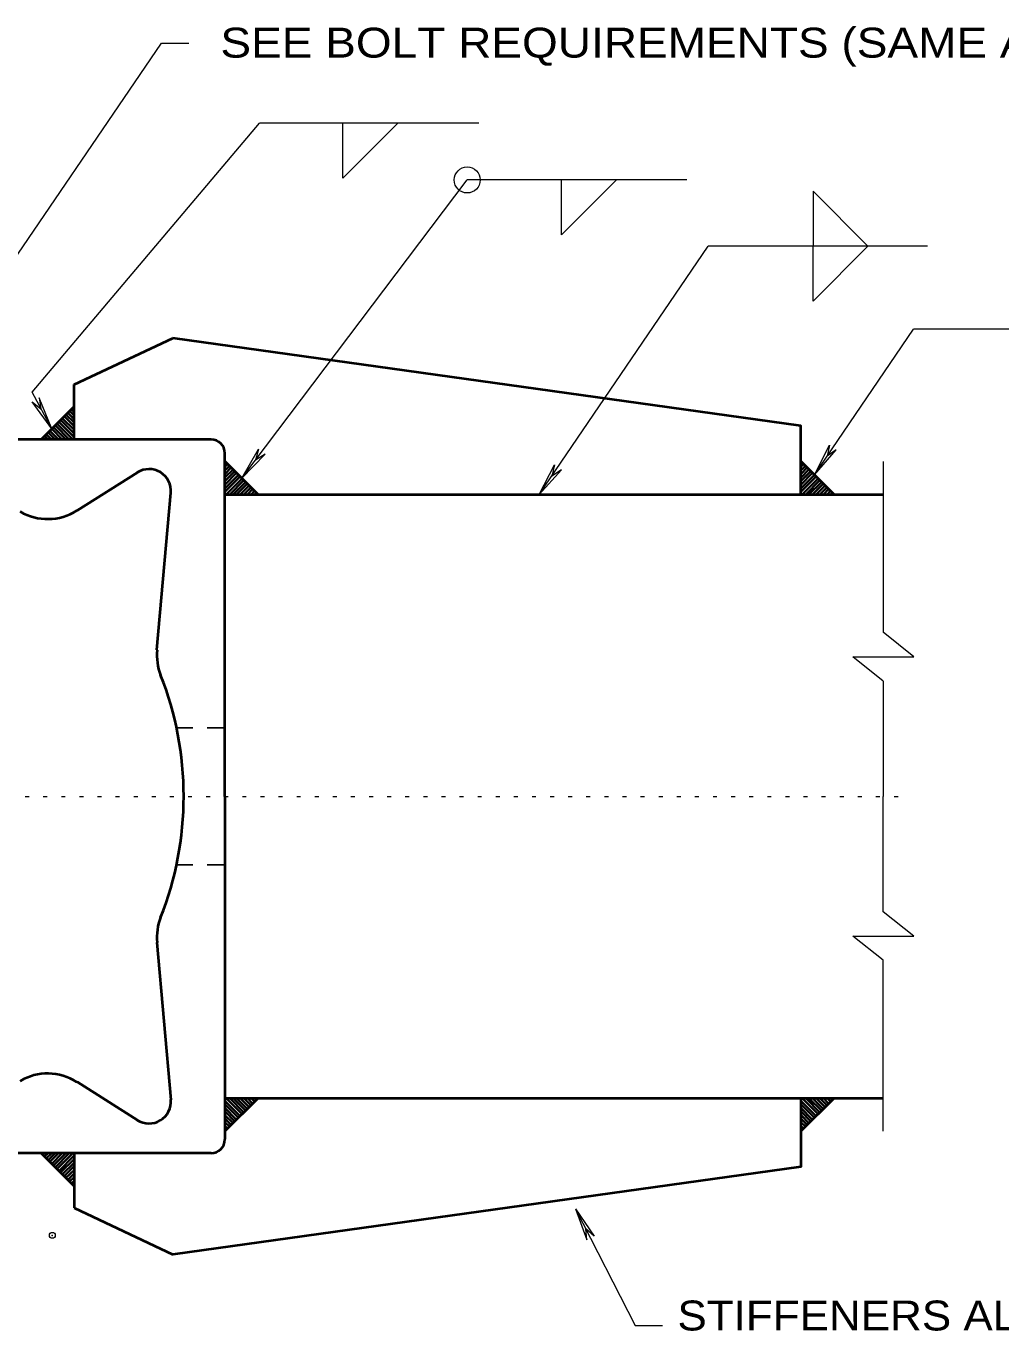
# Model space of a CAD drawing. Extents: x 312583 to 312854, y 144419 to 144597.
# Drawn here: x 312636.81 to 312661.58, y 144488.79 to 144521.92 of the extents above; entities that cross this region are included whole.
import ezdxf

# ---------------------------------------------------------------- set-up
doc = ezdxf.new("R2010")
doc.units = 0
doc.header["$LTSCALE"] = 0.3
doc.header["$PDMODE"] = 32
doc.header["$PDSIZE"] = 0.15
doc.linetypes.add('DOTTED', pattern=[1.5, 0.3, -1.2])
doc.linetypes.add('SHORT_DASHED', pattern=[2.7, 1.5, -1.2])
doc.layers.add('1', color=7, linetype='Continuous', lineweight=35)
doc.layers.add('2', color=7, linetype='Continuous', lineweight=13)

msp = doc.modelspace()

# ---------------------------------------------------------------- linework, layer by layer
at = {"layer": '1', "lineweight": 40}
for p, q in [((312638.0305, 144512.8216), (312640.5451, 144514.0023)), ((312638.0305, 144511.4263), (312638.0305, 144512.8216)), ((312637.1948, 144511.4263), (312638.0305, 144512.2619)), ((312641.5188, 144511.4263), (312635.2398, 144511.4263)), ((312641.8638, 144502.3643), (312641.8638, 144511.0813)), ((312642.7071, 144510.0309), (312641.8638, 144510.8743)), ((312657.3428, 144510.0309), (312656.4995, 144510.8743)), ((312638.1071, 144509.6246), (312639.6405, 144510.5906)), ((312640.1388, 144506.0826), (312640.4915, 144510.0693)), ((312641.8638, 144510.0309), (312658.5925, 144510.0309)), ((312641.8638, 144502.3643), (312641.8638, 144493.6549)), ((312640.1388, 144498.6536), (312640.4915, 144494.6593)), ((312638.1071, 144495.1116), (312639.6405, 144494.1456)), ((312641.8638, 144494.6976), (312658.5925, 144494.6976)), ((312642.7071, 144494.6976), (312641.8638, 144493.8619)), ((312657.3428, 144494.6976), (312656.4995, 144493.8619)), ((312641.5188, 144493.3023), (312635.2398, 144493.3023)), ((312637.1948, 144493.3023), (312638.0305, 144492.4666)), ((312638.0305, 144493.3023), (312638.0305, 144491.9146)), ((312638.0305, 144491.9146), (312640.5451, 144490.7263))]:
    msp.add_line(p, q, dxfattribs=at)
at = {"layer": '1'}
for p, q in [((312638.0305, 144511.6716), (312637.7315, 144511.9706)), ((312638.0305, 144511.7636), (312637.7775, 144512.0166)), ((312638.0305, 144511.8556), (312637.8235, 144512.0626)), ((312638.0305, 144511.9399), (312637.8695, 144512.1009)), ((312638.0305, 144512.0319), (312637.9155, 144512.1546)), ((312638.0305, 144512.1239), (312637.9615, 144512.1929)), ((312638.0305, 144512.2159), (312638.0075, 144512.2389)), ((312637.6395, 144511.4263), (312637.4171, 144511.6486)), ((312637.7315, 144511.4263), (312637.4631, 144511.6946)), ((312637.8235, 144511.4263), (312637.5091, 144511.7406)), ((312637.9078, 144511.4263), (312637.5551, 144511.7866)), ((312637.9998, 144511.4263), (312637.5935, 144511.8326)), ((312638.0305, 144511.4876), (312637.6471, 144511.8786)), ((312638.0305, 144511.5796), (312637.6855, 144511.9246)), ((312637.2791, 144511.4263), (312637.2331, 144511.4723)), ((312637.3711, 144511.4263), (312637.2791, 144511.5183)), ((312637.4631, 144511.4263), (312637.3251, 144511.5566)), ((312637.5475, 144511.4263), (312637.3711, 144511.6026)), ((312641.8638, 144510.8206), (312641.8868, 144510.8436)), ((312641.8638, 144510.7286), (312641.9405, 144510.8053)), ((312641.8638, 144510.6366), (312641.9788, 144510.7593)), ((312641.8638, 144510.5446), (312642.0248, 144510.7133)), ((312641.8638, 144510.4603), (312642.0708, 144510.6673)), ((312641.8638, 144510.3683), (312642.1168, 144510.6213)), ((312656.4995, 144510.8206), (312656.5225, 144510.8436)), ((312656.4995, 144510.7286), (312656.5761, 144510.8053)), ((312656.4995, 144510.6366), (312656.6145, 144510.7593)), ((312656.4995, 144510.5446), (312656.6605, 144510.7133)), ((312656.4995, 144510.3683), (312656.7525, 144510.6213)), ((312656.5071, 144510.4603), (312656.7065, 144510.6673)), ((312641.8638, 144510.2763), (312642.1628, 144510.5753)), ((312641.8638, 144510.1843), (312642.2088, 144510.5293)), ((312641.8638, 144510.0999), (312642.2548, 144510.4833)), ((312641.8945, 144510.0309), (312642.3008, 144510.4373)), ((312641.9865, 144510.0309), (312642.3468, 144510.3913)), ((312642.0708, 144510.0309), (312642.3851, 144510.3453)), ((312642.1628, 144510.0309), (312642.4311, 144510.2993)), ((312656.4995, 144510.2763), (312656.7985, 144510.5753)), ((312656.4995, 144510.1843), (312656.8445, 144510.5293)), ((312656.4995, 144510.0999), (312656.8905, 144510.4833)), ((312656.5301, 144510.0309), (312656.9365, 144510.4373)), ((312656.6221, 144510.0309), (312656.9825, 144510.3913)), ((312656.7065, 144510.0309), (312657.0285, 144510.3453)), ((312656.7985, 144510.0309), (312657.0668, 144510.2993)), ((312642.2548, 144510.0309), (312642.4771, 144510.2609)), ((312642.3468, 144510.0309), (312642.5231, 144510.2073)), ((312642.4388, 144510.0309), (312642.5691, 144510.1689)), ((312642.5308, 144510.0309), (312642.6151, 144510.1229)), ((312642.6151, 144510.0309), (312642.6611, 144510.0769)), ((312656.8905, 144510.0309), (312657.1205, 144510.2609)), ((312656.9825, 144510.0309), (312657.1588, 144510.2073)), ((312657.0745, 144510.0309), (312657.2048, 144510.1689)), ((312657.1665, 144510.0309), (312657.2508, 144510.1229)), ((312657.2508, 144510.0309), (312657.2968, 144510.0769)), ((312641.8638, 144494.6363), (312642.2548, 144494.2453)), ((312641.8638, 144494.5443), (312642.2088, 144494.1993)), ((312641.8638, 144494.4523), (312642.1628, 144494.1533)), ((312641.8945, 144494.6976), (312642.3008, 144494.2913)), ((312641.9865, 144494.6976), (312642.3468, 144494.3373)), ((312642.0708, 144494.6976), (312642.3851, 144494.3833)), ((312642.1628, 144494.6976), (312642.4311, 144494.4293)), ((312642.2548, 144494.6976), (312642.4771, 144494.4753)), ((312642.3468, 144494.6976), (312642.5231, 144494.5213)), ((312642.4388, 144494.6976), (312642.5691, 144494.5673)), ((312642.5308, 144494.6976), (312642.6151, 144494.6133)), ((312642.6151, 144494.6976), (312642.6611, 144494.6516)), ((312656.4995, 144494.6363), (312656.8905, 144494.2453)), ((312656.4995, 144494.5443), (312656.8445, 144494.1993)), ((312656.4995, 144494.4523), (312656.7985, 144494.1533)), ((312656.5301, 144494.6976), (312656.9365, 144494.2913)), ((312656.6221, 144494.6976), (312656.9825, 144494.3373)), ((312656.7065, 144494.6976), (312657.0285, 144494.3833)), ((312656.7985, 144494.6976), (312657.0668, 144494.4293)), ((312656.8905, 144494.6976), (312657.1205, 144494.4753)), ((312656.9825, 144494.6976), (312657.1588, 144494.5213)), ((312657.0745, 144494.6976), (312657.2048, 144494.5673)), ((312657.1665, 144494.6976), (312657.2508, 144494.6133)), ((312657.2508, 144494.6976), (312657.2968, 144494.6516)), ((312641.8638, 144494.3679), (312642.1168, 144494.1073)), ((312641.8638, 144494.2683), (312642.0708, 144494.0689)), ((312641.8638, 144494.1839), (312642.0248, 144494.0229)), ((312641.8638, 144494.0919), (312641.9788, 144493.9769)), ((312656.4995, 144494.3679), (312656.7525, 144494.1073)), ((312656.4995, 144494.1839), (312656.6605, 144494.0229)), ((312656.4995, 144494.0919), (312656.6145, 144493.9769)), ((312656.5071, 144494.2683), (312656.7065, 144494.0689)), ((312641.8638, 144493.9999), (312641.9405, 144493.9309)), ((312641.8638, 144493.9079), (312641.8868, 144493.8849)), ((312656.4995, 144493.9999), (312656.5761, 144493.9309)), ((312656.4995, 144493.9079), (312656.5225, 144493.8849)), ((312637.2791, 144493.3023), (312637.2331, 144493.2639)), ((312637.3711, 144493.3023), (312637.2791, 144493.2179)), ((312637.4631, 144493.3023), (312637.3251, 144493.1719)), ((312637.5475, 144493.3023), (312637.3711, 144493.1259)), ((312637.6395, 144493.3023), (312637.4171, 144493.0799)), ((312637.7315, 144493.3023), (312637.4631, 144493.0339)), ((312637.8235, 144493.3023), (312637.5091, 144492.9879)), ((312637.9078, 144493.3023), (312637.5551, 144492.9419)), ((312637.9998, 144493.3023), (312637.5935, 144492.8959)), ((312638.0305, 144493.2409), (312637.6471, 144492.8499)), ((312638.0305, 144493.1489), (312637.6855, 144492.8116)), ((312638.0305, 144493.0569), (312637.7315, 144492.7579)), ((312638.0305, 144492.9726), (312637.7775, 144492.7196)), ((312638.0305, 144492.8729), (312637.8235, 144492.6736)), ((312638.0305, 144492.7886), (312637.8695, 144492.6276)), ((312638.0305, 144492.6966), (312637.9155, 144492.5816)), ((312638.0305, 144492.6046), (312637.9615, 144492.5356)), ((312638.0305, 144492.5126), (312638.0075, 144492.4896))]:
    msp.add_line(p, q, dxfattribs=at)
at = {"layer": '1', "lineweight": 13}
for p, q in [((312658.5925, 144510.8666), (312658.5925, 144506.5349)), ((312658.5925, 144505.2929), (312658.5925, 144502.3643)), ((312658.5925, 144499.4356), (312658.5925, 144502.3643)), ((312658.5925, 144493.8619), (312658.5925, 144498.2013))]:
    msp.add_line(p, q, dxfattribs=at)
at = {"layer": '1', "linetype": 'SHORT_DASHED', "lineweight": 25}
for p, q in [((312641.8638, 144504.1046), (312640.6371, 144504.1046)), ((312641.8638, 144500.6239), (312640.6371, 144500.6239))]:
    msp.add_line(p, q, dxfattribs=at)
at = {"layer": '1', "lineweight": 40}
for points in [[(312656.4995, 144510.0309), (312656.4995, 144511.7713), (312640.5451, 144514.0023)], [(312656.4995, 144494.6976), (312656.4995, 144492.9573), (312640.5451, 144490.7263)]]:
    msp.add_lwpolyline(points, dxfattribs=at)
for centre, radius, start, end in [((312641.516, 144511.0778), 0.3485, 0, 90), ((312639.9346, 144510.1164), 0.5576, 354.9816, 122.2056), ((312637.3601, 144510.801), 1.3939, 239.82421, 302.19008), ((312641.5283, 144505.9564), 1.3939, 174.98166, 201.59188), ((312632.4554, 144502.3657), 8.3636, 0, 21.59568), ((312632.4554, 144502.3657), 8.3636, 338.40432, 0), ((312641.5283, 144498.7749), 1.3939, 158.40812, 185.01834), ((312637.3601, 144493.9304), 1.3939, 57.80992, 120.17579), ((312639.9346, 144494.6149), 0.5576, 237.7944, 5.0184), ((312641.516, 144493.6535), 0.3485, 270, 0)]:
    msp.add_arc(centre, radius, start, end, dxfattribs=at)
at = {"layer": '2'}
for p, q in [((312648.3191, 144519.4609), (312642.7455, 144519.4609)), ((312642.2931, 144510.4449), (312648.0201, 144518.0196)), ((312653.6015, 144518.0196), (312648.0201, 144518.0196)), ((312649.8525, 144510.0309), (312654.1458, 144516.3329)), ((312659.7195, 144516.3329), (312654.1458, 144516.3329)), ((312656.8445, 144510.5293), (312659.3591, 144514.2246)), ((312664.9328, 144514.2246), (312659.3591, 144514.2246)), ((312636.9648, 144512.3846), (312637.1871, 144512.2006)), ((312637.4631, 144511.6946), (312636.9648, 144512.3846)), ((312637.1488, 144512.4843), (312637.1871, 144512.2006)), ((312637.4631, 144511.6946), (312637.1488, 144512.4843)), ((312642.2931, 144510.4449), (312642.7148, 144511.1809)), ((312642.2931, 144510.4449), (312642.8835, 144511.0506)), ((312642.7148, 144511.1809), (312642.6381, 144510.9049)), ((312642.8835, 144511.0506), (312642.6381, 144510.9049)), ((312656.8445, 144510.5293), (312657.2278, 144511.2806)), ((312656.8445, 144510.5293), (312657.3965, 144511.1656)), ((312657.2278, 144511.2806), (312657.1665, 144511.0046)), ((312657.3965, 144511.1656), (312657.1665, 144511.0046)), ((312649.8525, 144510.0309), (312650.2435, 144510.7823)), ((312649.8525, 144510.0309), (312650.4198, 144510.6596)), ((312650.2435, 144510.7823), (312650.1745, 144510.4986)), ((312650.4198, 144510.6596), (312650.1745, 144510.4986)), ((312650.7725, 144491.8916), (312652.2905, 144488.9246)), ((312650.7725, 144491.8916), (312651.0638, 144491.1019)), ((312650.7725, 144491.8916), (312651.2478, 144491.1939)), ((312651.0638, 144491.1019), (312651.0331, 144491.3856)), ((312651.2478, 144491.1939), (312651.0331, 144491.3856)), ((312652.2905, 144488.9246), (312652.9881, 144488.9246))]:
    msp.add_line(p, q, dxfattribs=at)
at = {"layer": '2', "linetype": 'DOTTED'}
msp.add_line((312633.5685, 144502.3643), (312659.2901, 144502.3643), dxfattribs=at)
at = {"layer": '2'}
for points in [[(312635.7841, 144514.9376), (312640.2538, 144521.4926), (312640.9515, 144521.4926)], [(312637.4631, 144511.6946), (312636.9648, 144512.6299), (312642.7455, 144519.4609)], [(312646.2568, 144519.4609), (312644.8615, 144518.0656), (312644.8615, 144519.4609)], [(312651.8151, 144518.0196), (312650.4198, 144516.6243), (312650.4198, 144518.0196)], [(312658.2015, 144516.3329), (312656.8138, 144517.7283), (312656.8138, 144516.3329)], [(312658.2015, 144516.3329), (312656.8138, 144514.9376), (312656.8138, 144516.3329)], [(312658.5925, 144505.2929), (312657.8181, 144505.9063), (312659.3668, 144505.9063), (312658.5925, 144506.5349)], [(312658.5925, 144498.2013), (312657.8181, 144498.8146), (312659.3668, 144498.8146), (312658.5925, 144499.4356)]]:
    msp.add_lwpolyline(points, dxfattribs=at)
msp.add_circle((312648.0229, 144518.0168), 0.3302, dxfattribs=at)
msp.add_point((312637.4785, 144491.2169), dxfattribs=at)

# ---------------------------------------------------------------- texts
for s, width, p in [('SEE BOLT REQUIREMENTS (SAME AS ABOVE)', 1.15, (312641.75, 144521.1232)), ('STIFFENERS ALUM.', 1.1, (312653.3638, 144488.8009))]:
    msp.add_text(s, height=0.76, dxfattribs=dict(at, width=width)).set_placement(p)

doc.saveas('drawing.dxf')
